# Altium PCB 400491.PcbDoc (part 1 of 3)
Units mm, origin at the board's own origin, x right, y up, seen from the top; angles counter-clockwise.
Board outline 85.6 x 53.98 mm, 4 copper layers (Top Layer, Mid-Layer 1, Mid-Layer 2, Bottom Layer), stack 1.528 mm thick; 280 components, 167 nets, 927 pads, 859 vias.
Unrouted connection lines stored in the file: 24.
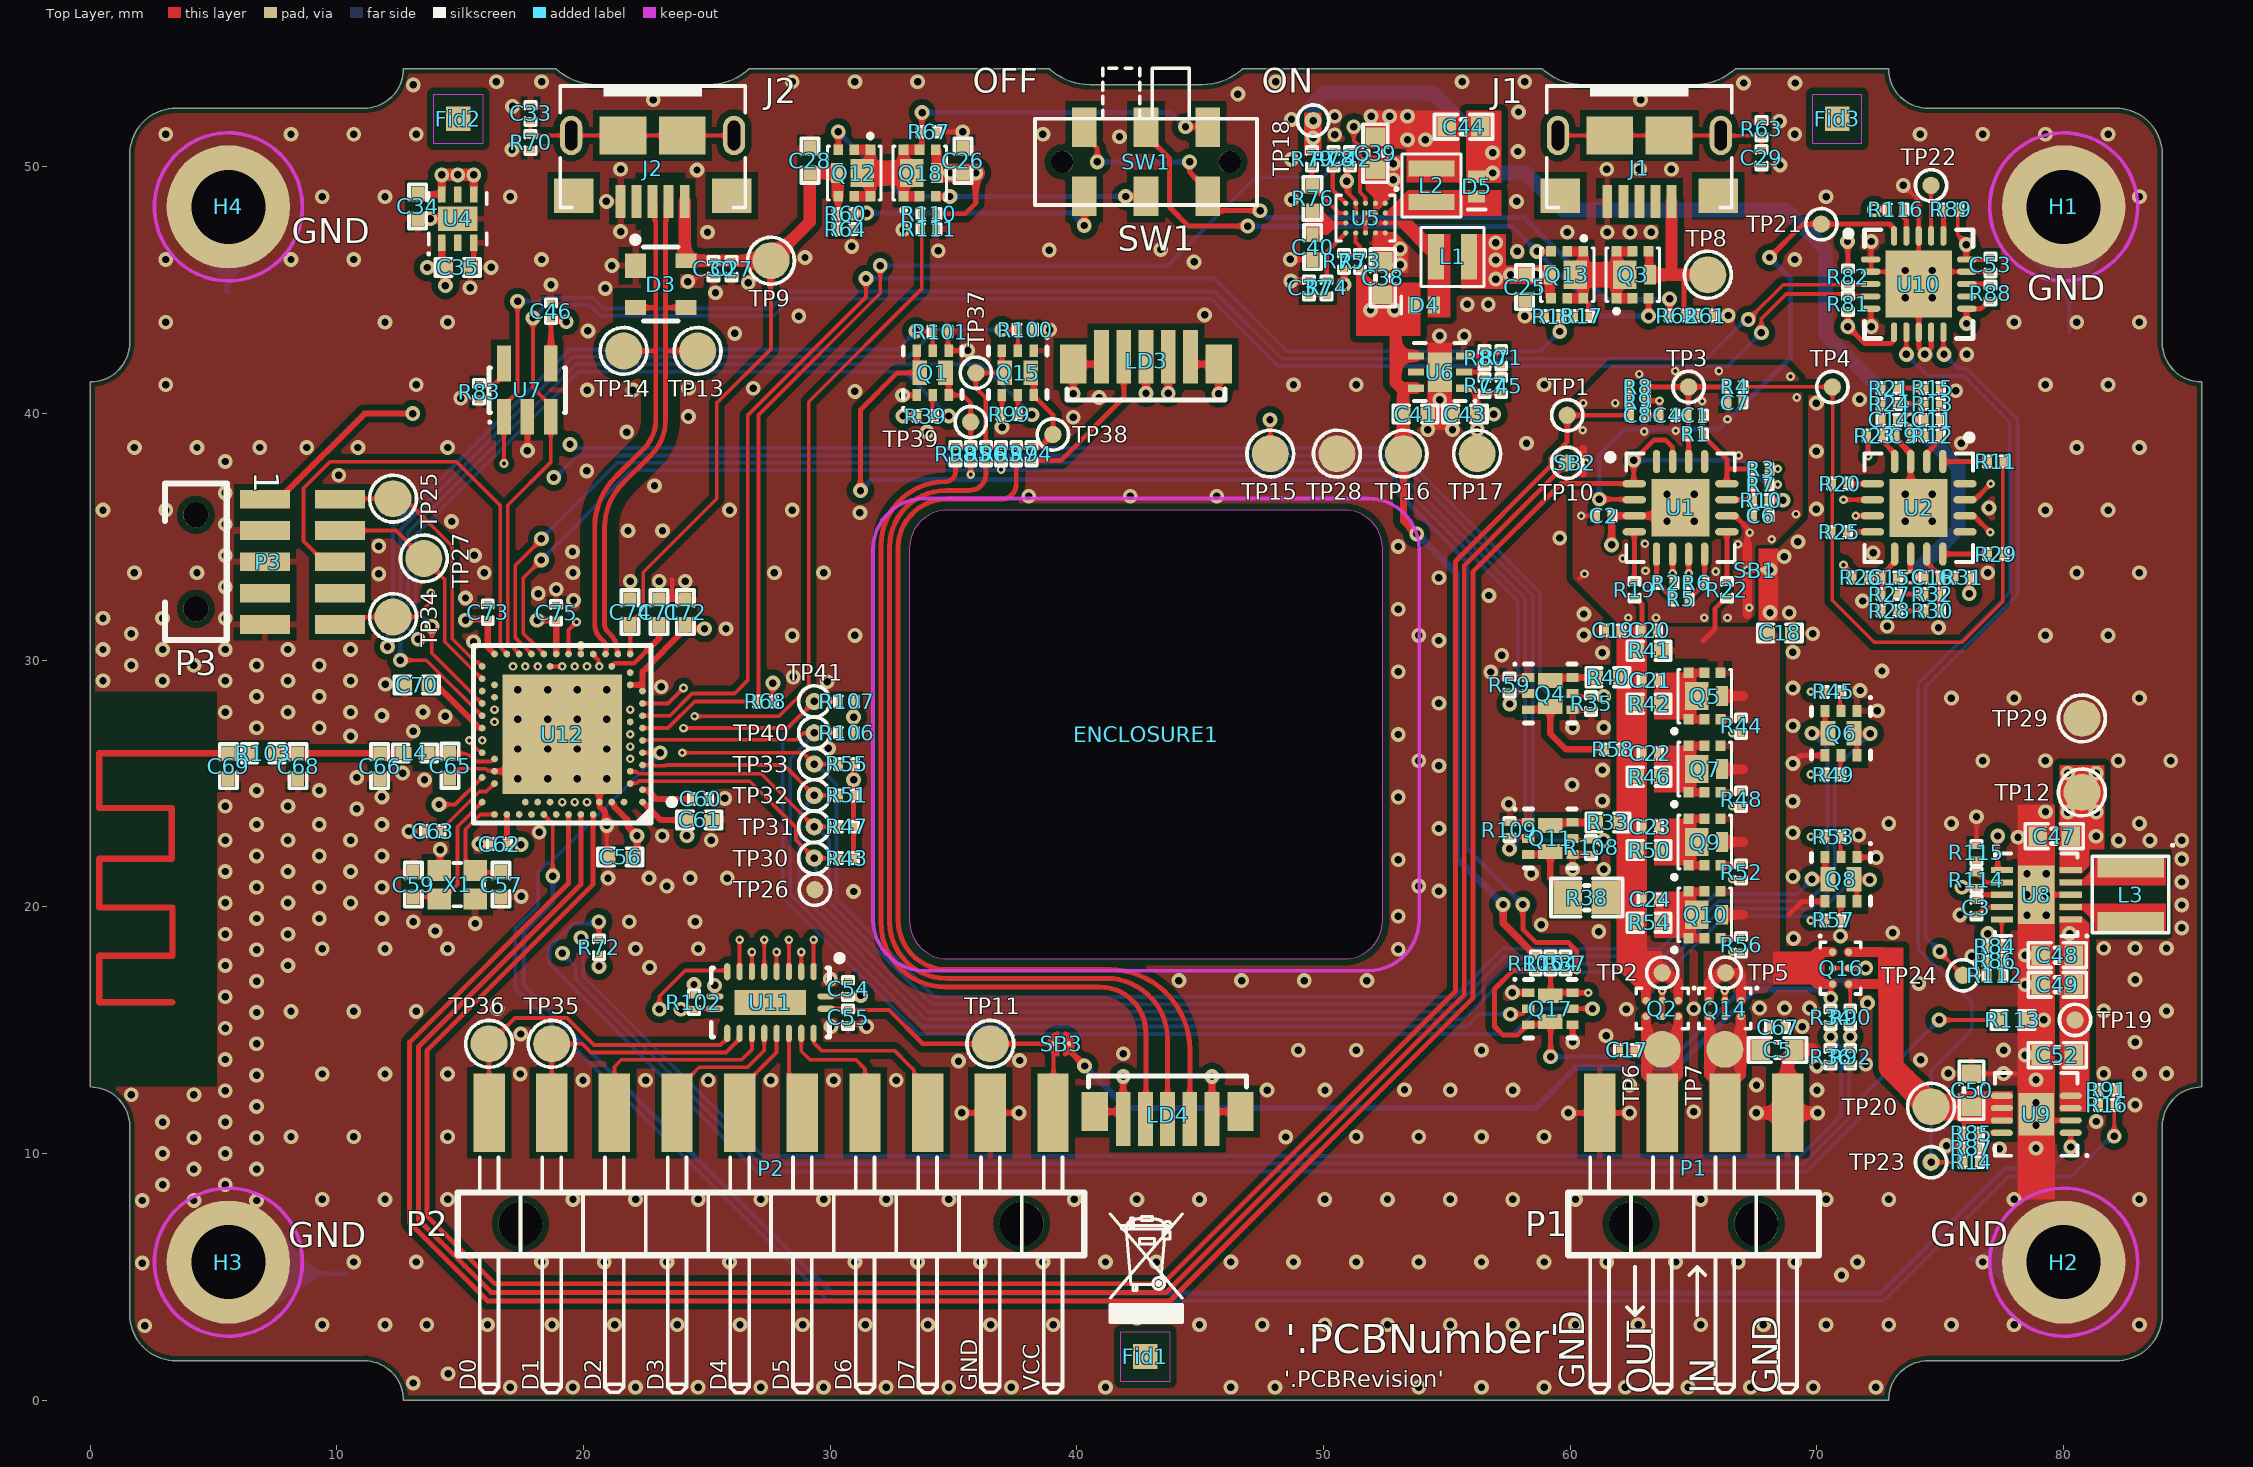
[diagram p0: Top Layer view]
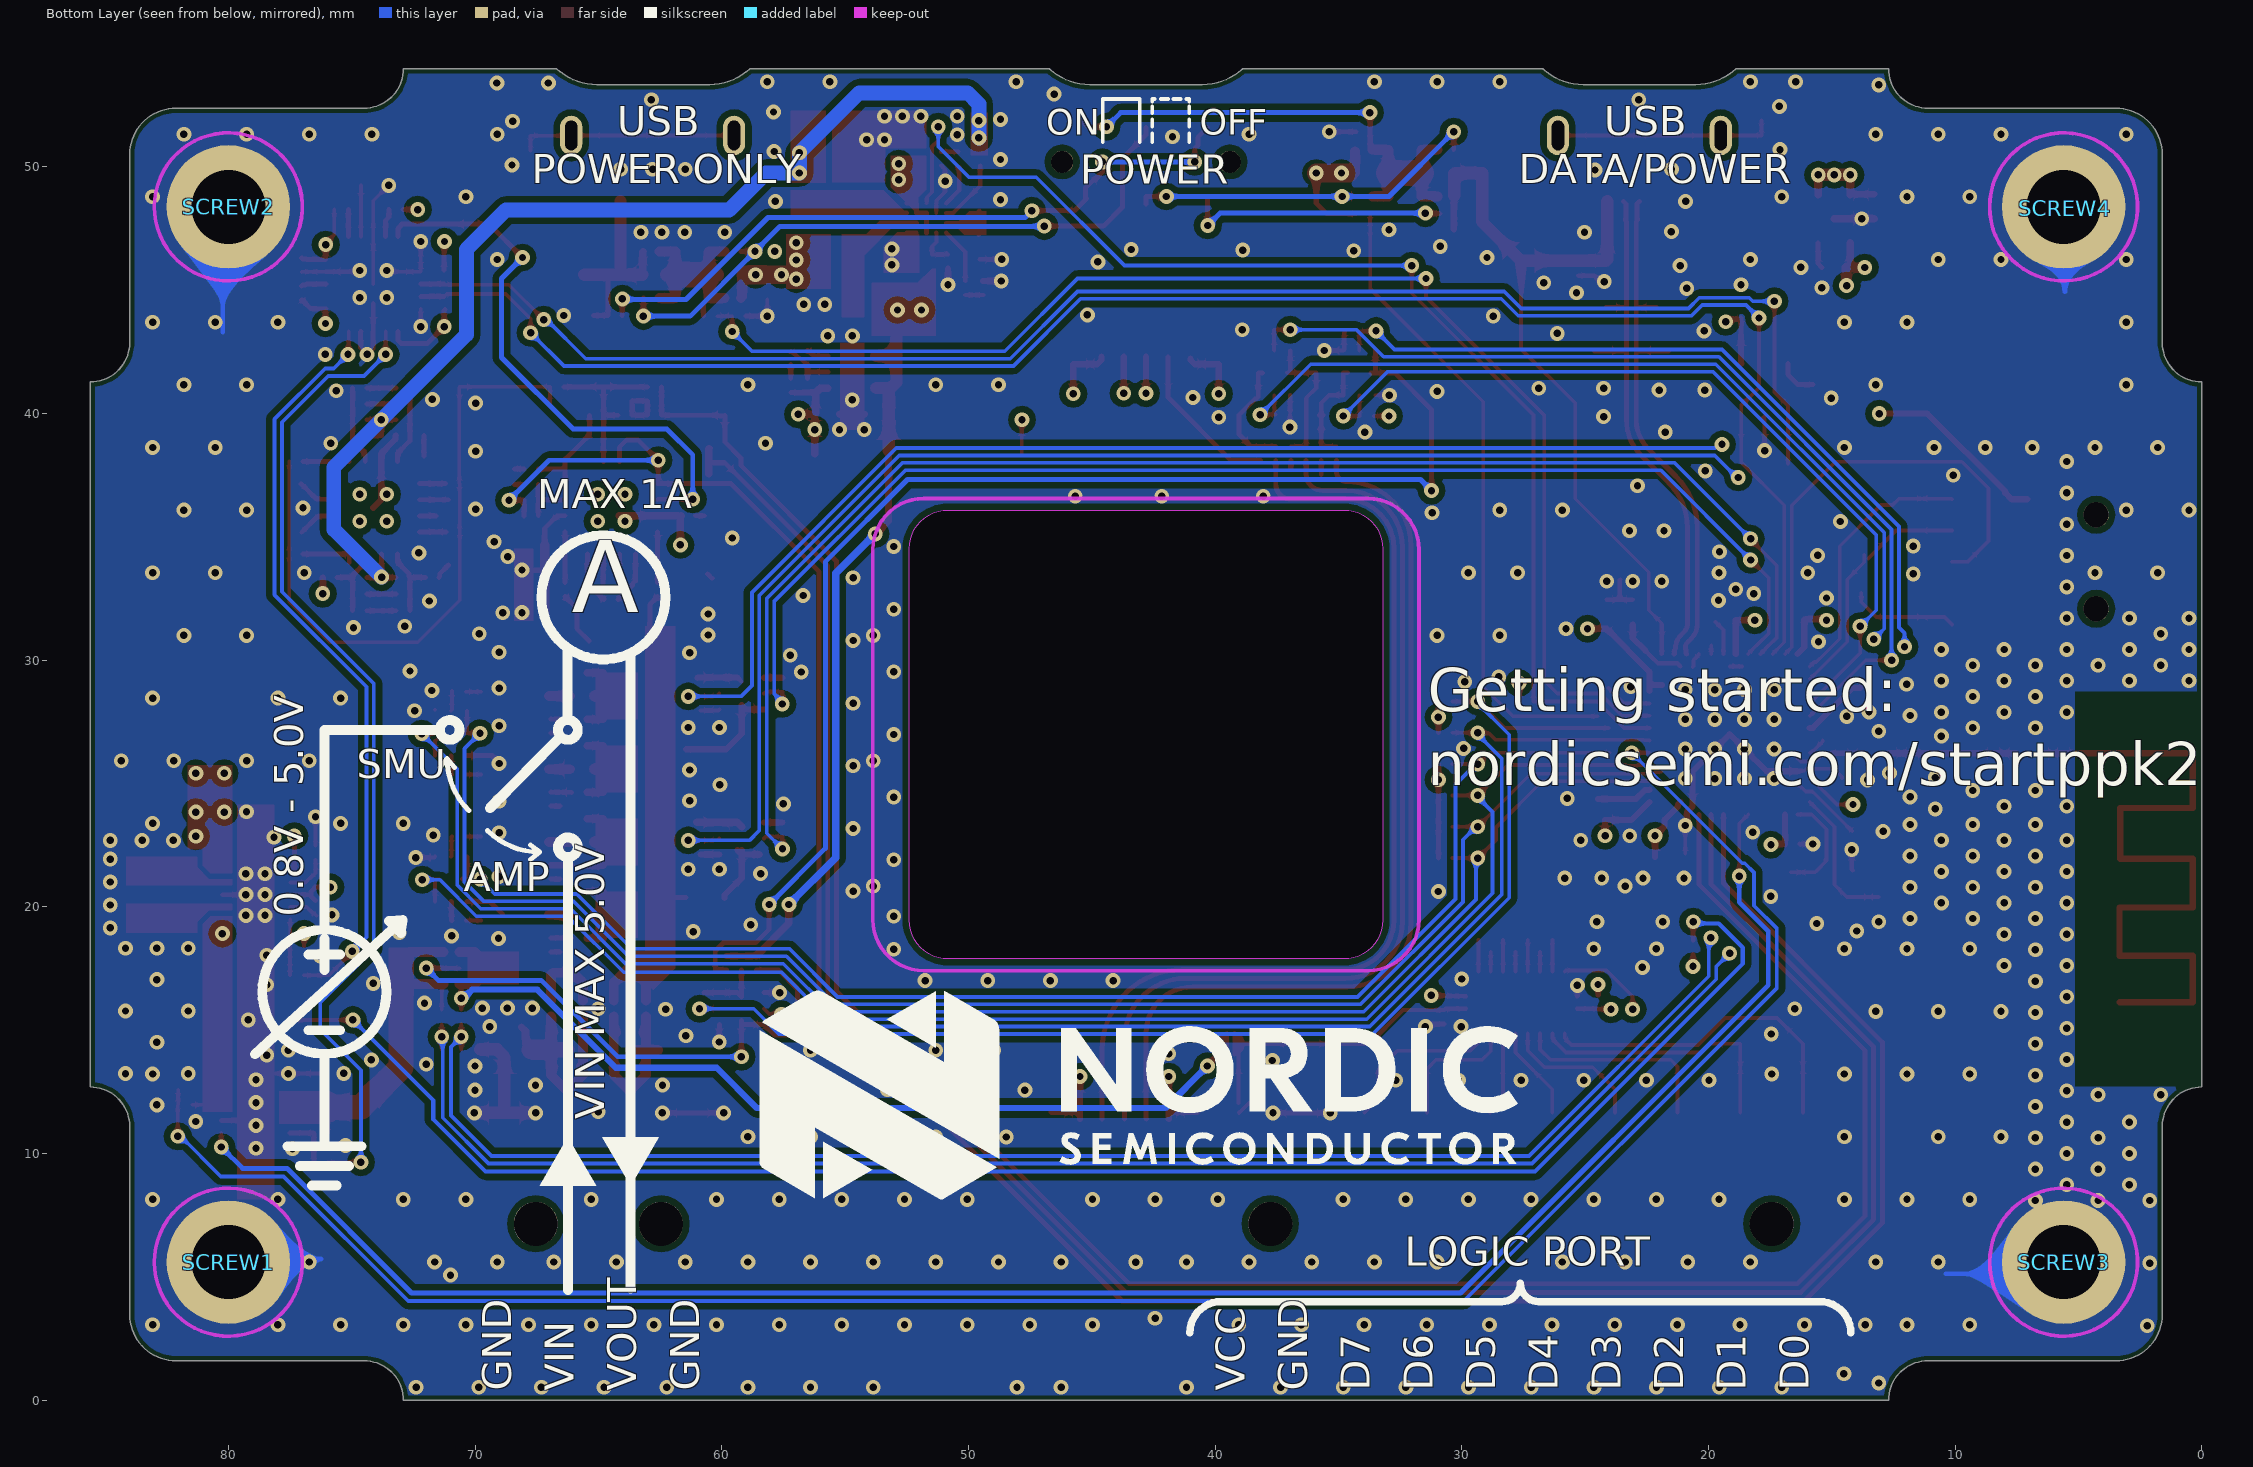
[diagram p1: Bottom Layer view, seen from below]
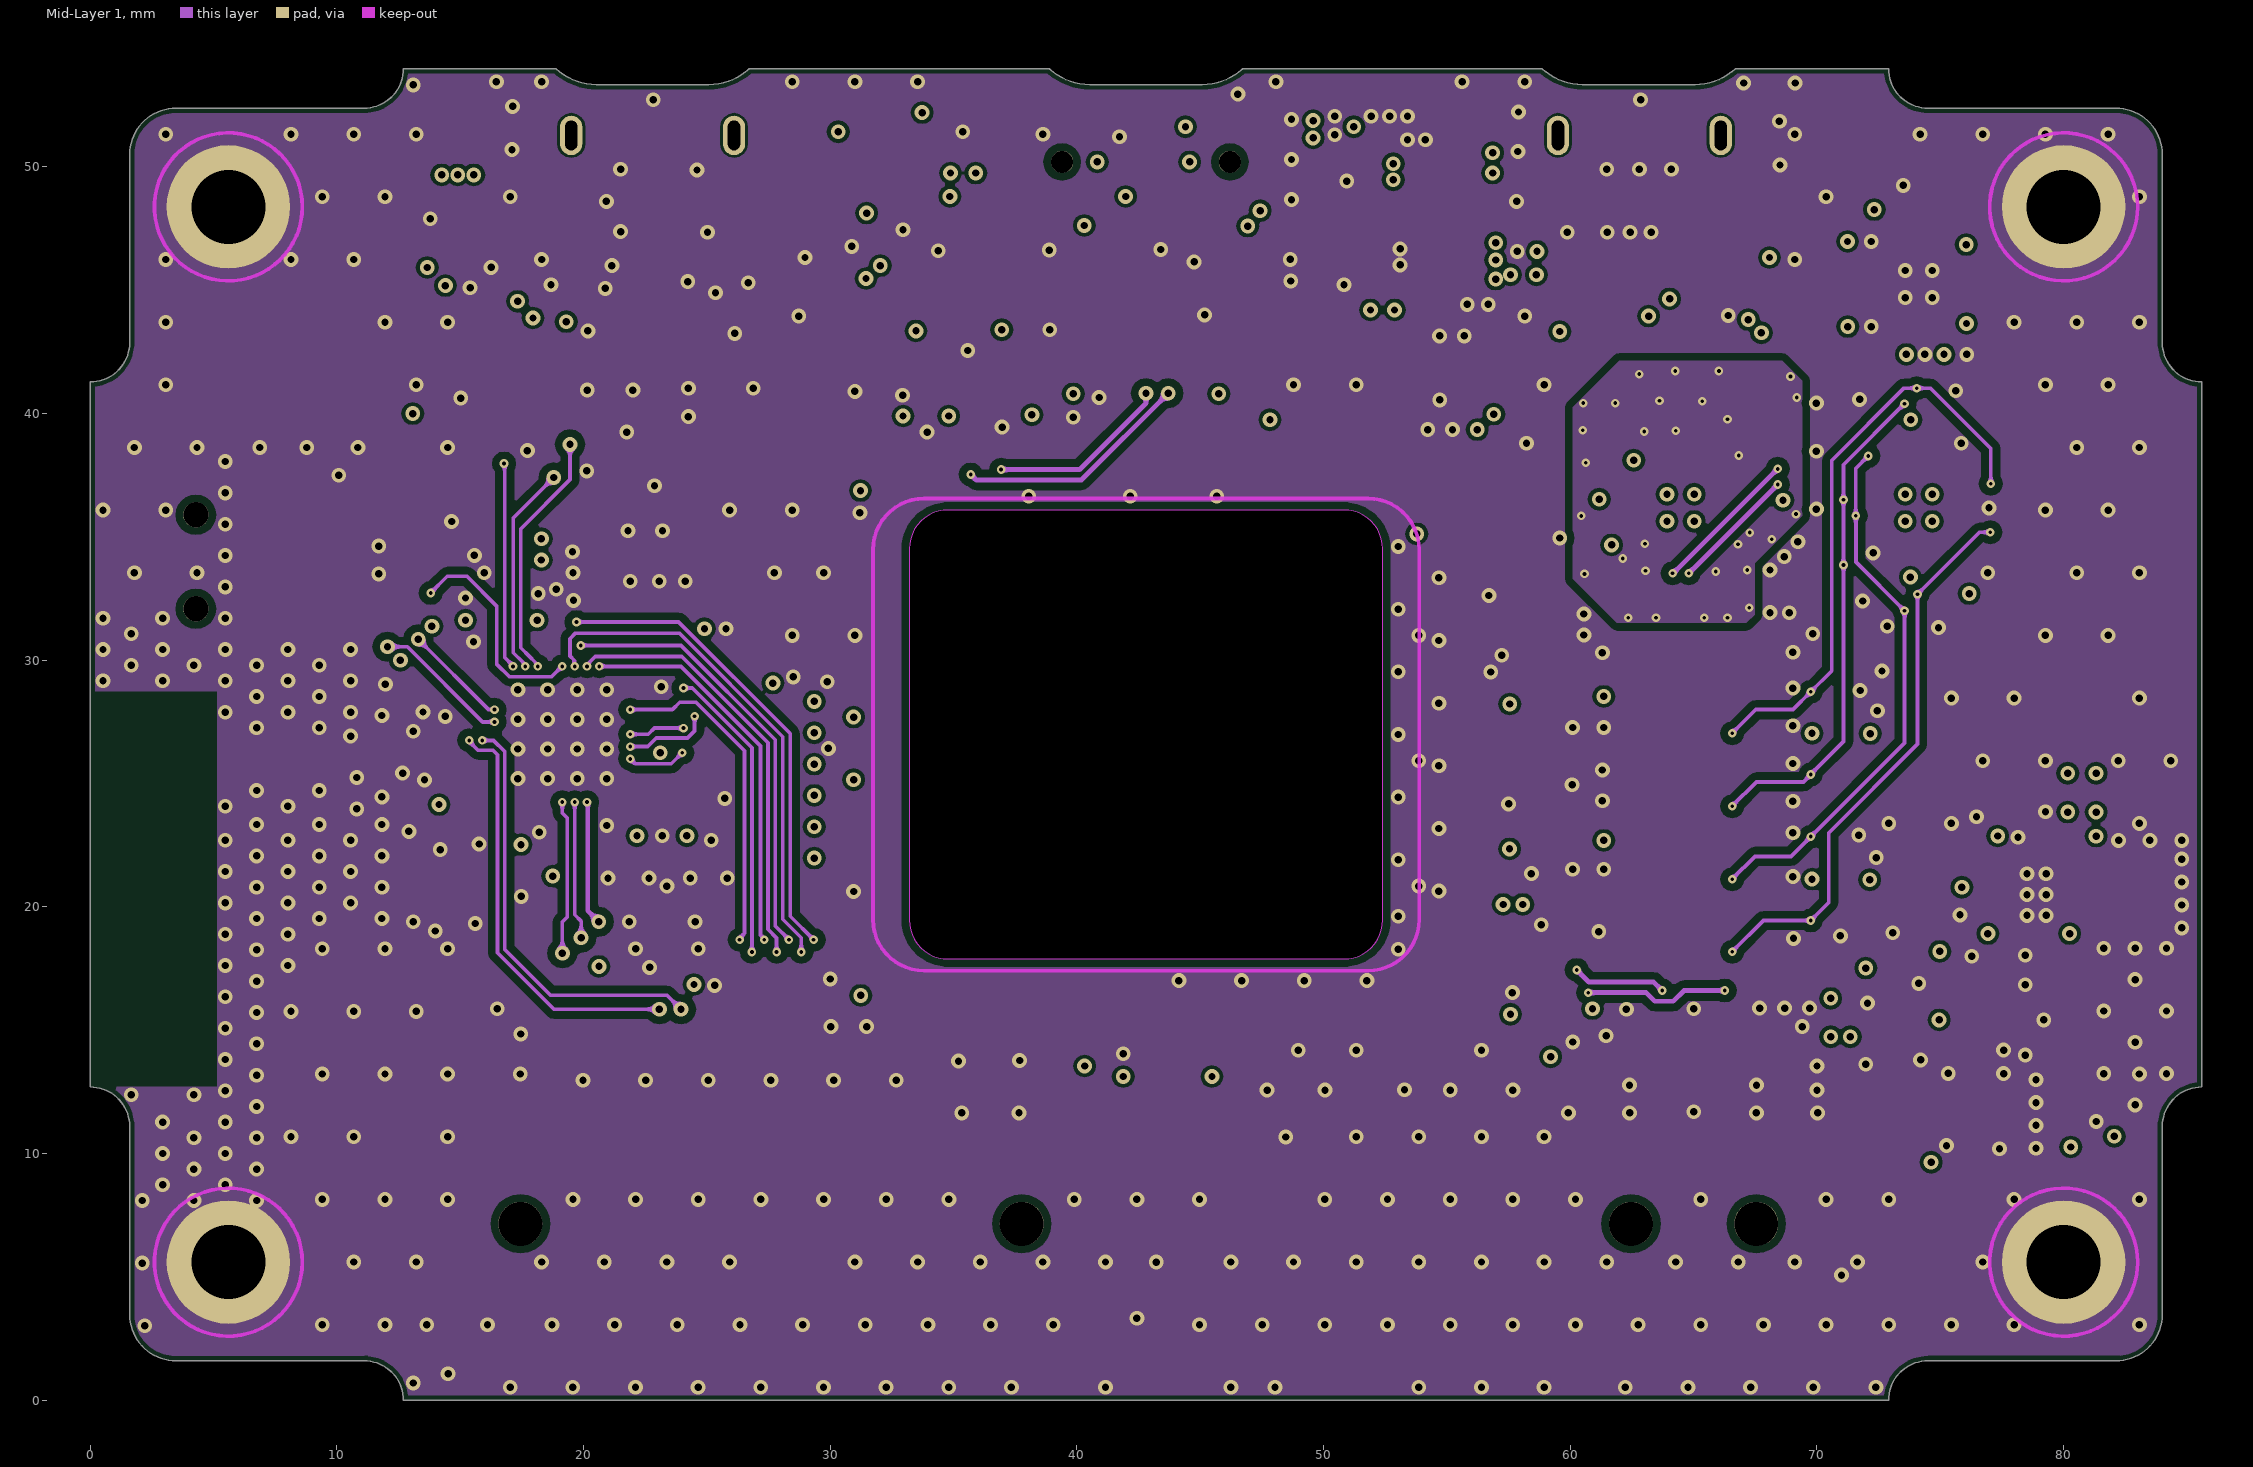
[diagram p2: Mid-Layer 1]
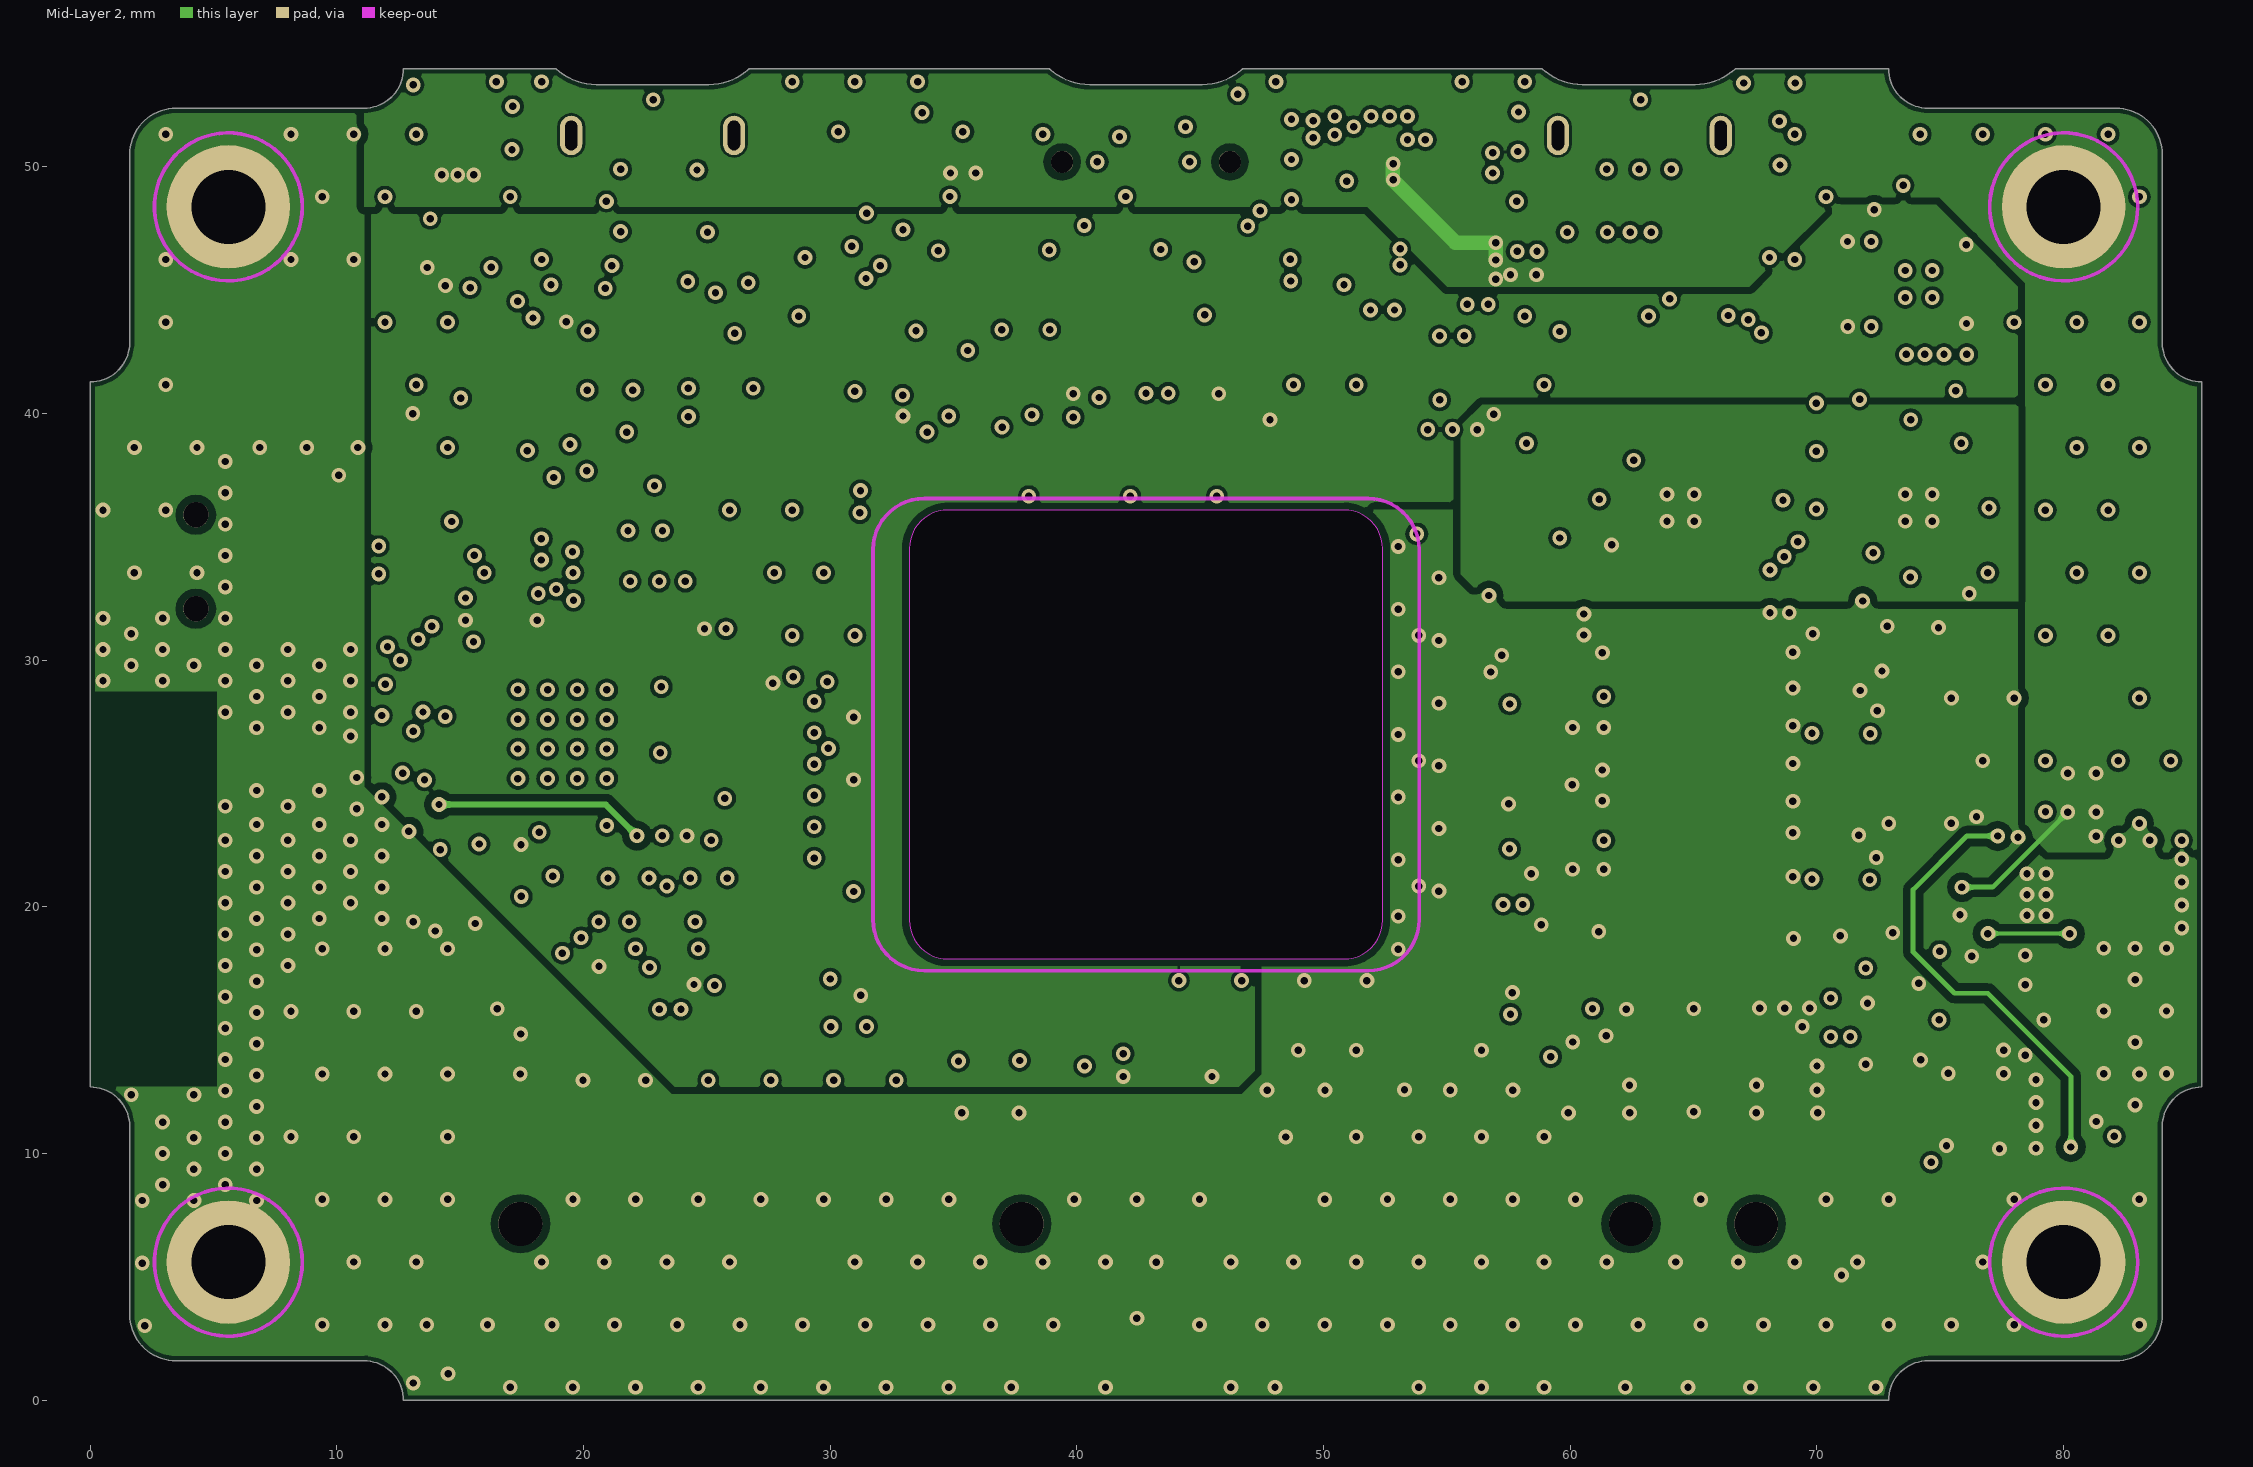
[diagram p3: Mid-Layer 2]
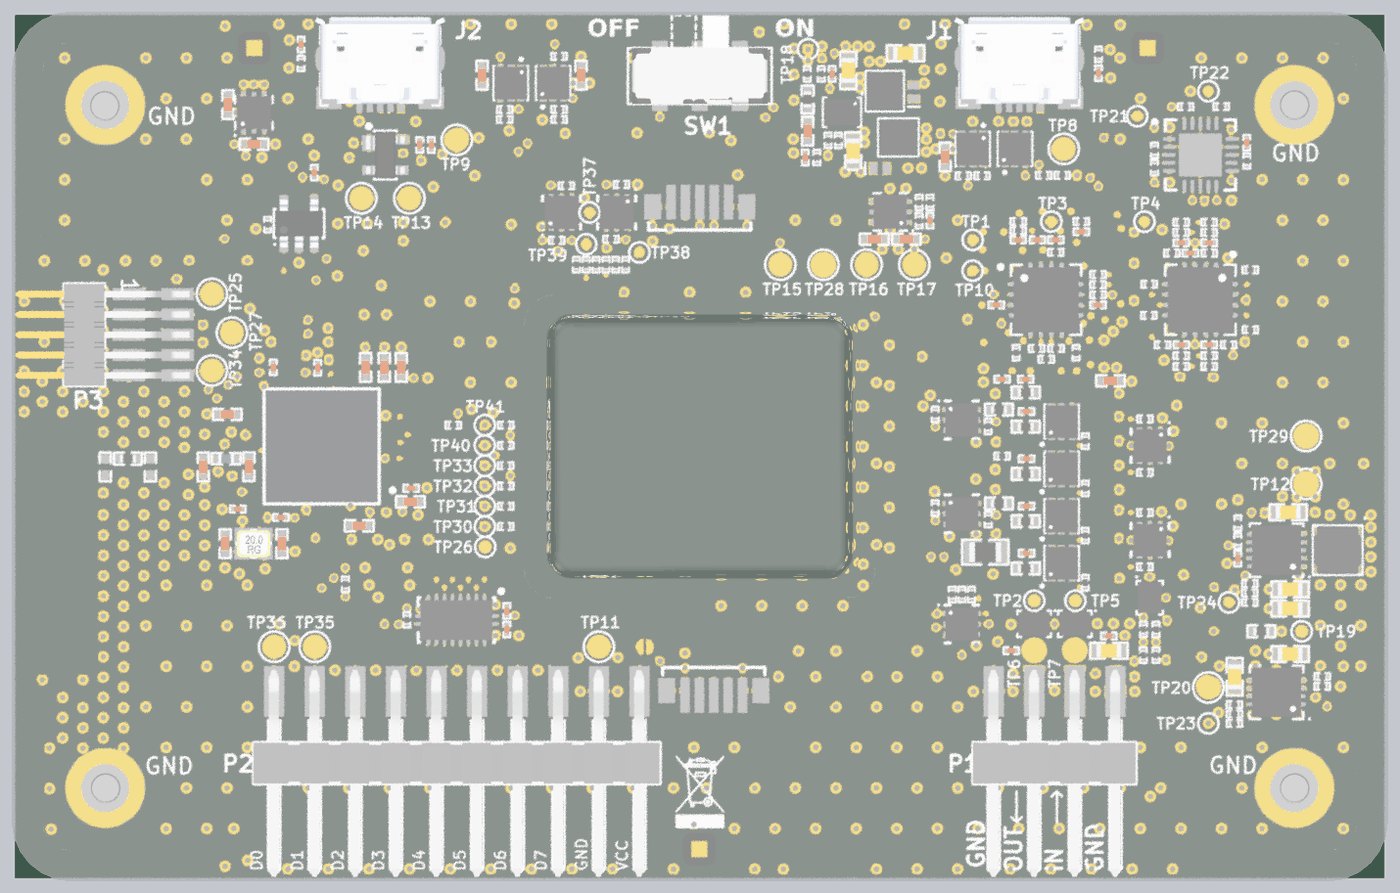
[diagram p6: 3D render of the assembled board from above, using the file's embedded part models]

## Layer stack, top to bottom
Top Solder: solder mask 0.013, SM-003, Dk 3.4
Top Layer: signal copper 0.046
Dielectric1: prepreg 0.073, FR-4, Dk 4.18
Mid-Layer 1: signal copper 0.03
Dielectric2: core 1.23, FR-4, Dk 4.74
Mid-Layer 2: signal copper 0.03
Dielectric3: prepreg 0.073, FR-4, Dk 4.18
Bottom Layer: signal copper 0.046
Bottom Solder: solder mask 0.013, SM-003, Dk 3.4

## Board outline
1.6,11.1 ccw(c0,11.1) 0,12.7 0,41.28 ccw(c0,42.88) 1.6,42.88 1.6,50.5 cw(c3.48,50.5) 3.48,52.38 11.1,52.38 ccw(c11.1,53.98) 12.7,53.98 18.881,53.98 ccw(c20.518,55.736) 20.518,53.336 25.082,53.336 ccw(c25.082,55.736) 26.719,53.98 38.881,53.98 ccw(c40.518,55.735) 40.518,53.335 45.082,53.335 ccw(c45.082,55.735) 46.719,53.98 58.856,53.98 ccw(c60.493,55.736) 60.493,53.336 65.057,53.336 ccw(c65.057,55.736) 66.694,53.98 72.9,53.98 ccw(c74.5,53.98) 74.5,52.38 82.12,52.38 cw(c82.12,50.5) 84,50.5 84,42.88 ccw(c85.6,42.88) 85.6,41.28 85.6,12.7 ccw(c85.6,11.1) 84,11.1 84,3.48 cw(c82.12,3.48) 82.12,1.6 74.5,1.6 ccw(c74.5,0) 72.9,0 12.7,0 ccw(c11.1,0) 11.1,1.6 3.48,1.6 cw(c3.48,3.48) 1.6,3.48
cut-out: 33.2,19.47 ccw(c34.78,19.47) 34.78,17.89 50.82,17.89 ccw(c50.82,19.47) 52.4,19.47 52.4,34.51 ccw(c50.82,34.51) 50.82,36.09 34.78,36.09 ccw(c34.78,34.51) 33.2,34.51

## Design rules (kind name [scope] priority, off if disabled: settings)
AcuteAngle [All] p1: minimum=6.00000000000000E+0001 checktracksonly=TRUE
AssemblyTestPointUsage [All] p1: valid=2 allowmultiple=TRUE
AssemblyTestpoint [All] p1: testpointundercomponent=TRUE minsize=1 maxsize=2.54 preferedsize=1.5 minholesize=0 maxholesize=1 preferedholesize=0.3 testpointgrid=0.025 usegrid=FALSE gridtolerance=0 allowsidetop=TRUE allowsidebottom=TRUE minspacing=2 compbodyclearance=0.127
BoardOutlineClearance [not ( HasFootprint('Switch-Slide-RA-J-Lead-DPDT-8.5x3.5mm') or HasFootprint('USB-Micro-B-RA-SMD-PiP') or HasFootprint('LIST_ANG_1x4') or HasFootprint('MSL0104') or IsKeepOut or InComponent('J7') or InComponent('J1'))] p1: gap=0.2 ignorepadtopadclearanceinfootprint=FALSE
Clearance "Stitching GND" [IsStitchingVia and InNet('GND') vs (IsVia and (Not IsStitchingVia)) Or IsPad] p1: gap=0.15 ignorepadtopadclearanceinfootprint=FALSE
Clearance ANT_Clerance [InNet('ANT') or InNet('RF')] p2: gap=0.25 ignorepadtopadclearanceinfootprint=FALSE
Clearance Clearance_USB [InAnyDifferentialPair vs InPolygon] p3: gap=0.5 ignorepadtopadclearanceinfootprint=FALSE
Clearance Polygon_Clearance_Outer [(InNamedPolygon('Top_Layer-GND')) or (InNamedPolygon('Bottom_Layer-GND'))] p4: gap=0.254 ignorepadtopadclearanceinfootprint=FALSE
Clearance Polygon_Clearance_Inner [InPoly and OnMid] p5: gap=0.3 ignorepadtopadclearanceinfootprint=FALSE
Clearance Clearance_MCU [TouchesRoom('nRF5')] p6: gap=0.145 ignorepadtopadclearanceinfootprint=FALSE
Clearance [All] p7: gap=0.15 ignorepadtopadclearanceinfootprint=FALSE
ComponentClearance [All] p1 off: gap=0.254 collisioncheckmode=3 verticalgap=0.254 showdistances=FALSE
DiffPairsRouting [InDifferentialPair('RFD')] p1: maxlimit=0.2 minlimit=0.15 mostfreqgap=0.18 toplayer_minwidth=0.2 toplayer_maxwidth=0.22 toplayer_prefwidth=0.217 midlayer1_minwidth=0.2 midlayer1_maxwidth=0.22 midlayer1_prefwidth=0.217 midlayer2_minwidth=0.2 midlayer2_maxwidth=0.22 midlayer2_prefwidth=0.217 bottomlayer_minwidth=0.2 bottomlayer_maxwidth=0.22 bottomlayer_prefwidth=0.217 maxuncoupledlength=12.7
FabricationTestPointUsage TestPointUsage [All] p1: valid=2 allowmultiple=FALSE
FabricationTestpoint Testpoint [All] p1: side=3 testpointundercomponent=TRUE minsize=0.75 maxsize=2.54 preferedsize=1.524 minholesize=0 maxholesize=1.016 preferedholesize=0.813 testpointgrid=0.025 allowsidetop=TRUE allowsidebottom=TRUE usegrid=TRUE gridtolerance=0
Height [All] p1 off: minheight=0 maxheight=25.4 prefheight=12.7
HoleSize [All] p1: absolutevalues=TRUE maxlimit=5 minlimit=0.15 maxpercent=80.000 minpercent=20.000
HoleToHoleClearance [All] p1: gap=0.254 allowstackedmicrovias=FALSE
MaxMinImpedance [InNet('ANT')] p1: minimum=45,00 maximum=55,00
MinimumAnnularRing [All] p1 off: minimumring=0.152
MinimumSolderMaskSliver [All] p1: minsoldermaskwidth=0.08
NetAntennae [not InNet('ANT')] p1: netantennaetolerance=0
PolygonConnect PolygonConnect_TP [HasFootprint('TP_SMD_Ø1.0mm') or HasFootprint('TP_SMD_Ø1.5mm')] p1: connectstyle=Direct reliefconductorwidth=0.254 reliefentries=4 polygonreliefangle="90 Angle" airgapwidth=0.254
PolygonConnect [All] p2: thpad.connectstyle=Relief thpad.reliefconductorwidth=0.254 thpad.reliefentries=4 thpad.polygonreliefangle="90 Angle" thpad.airgapwidth=0.254 smdpad.connectstyle=Relief smdpad.reliefconductorwidth=0.254 smdpad.reliefentries=4 smdpad.polygonreliefangle="90 Angle" smdpad.airgapwidth=0.254 via.connectstyle=Direct via.reliefconductorwidth=0.254 via.reliefentries=4 via.polygonreliefangle="90 Angle" via.airgapwidth=0.254
ReturnPath [All] p1: impedanceprofileid={5BC9D8EB-500C-4DB7-B910-E6E0F3DAAD07} _gaplimit=0
RoomDefinition nRF5 [False] p1: confinementstyle=ConfineIn formatcopy=TRUE lockcomponents=FALSE outline 15.625,30.375 22.8,30.375 22.8,23.5 15.625,23.5
RoutingVias [All] p1: holewidth=0.3 width=0.6 viastyle="Through Hole" minholewidth=0.15 minwidth=0.35 maxholewidth=0.7 maxwidth=1.27
SilkToSilkClearance [All] p1: silktosilkclearance=0
SilkToSolderMaskClearance SilkscreenOverComponentPads [IsPad] p1: minsilkscreentomaskgap=0 clearancetoexposedcopper=TRUE
SolderMaskExpansion SolderMaskExpansion_VIA [IsVia and not IsAssyTestpoint] p1: expansion=-1 istentingtop=FALSE
SolderMaskExpansion [All] p2: expansion=0.06 istentingtop=FALSE
UnRoutedNet [All] p1: checkbadconnections=TRUE
ViasUnderSMD [All] p1: allowed=FALSE
Width Width_MCU [TouchesRoom('nRF5')] p1: maxlimit=0.5 minlimit=0.145 preferedwidth=0.2
Width Width_USB [InNet('RFD_N') or InNet('RFD_P')] p2: maxlimit=0.254 minlimit=0.091 preferedwidth=0.254 toplayer_maxwidth=0.233 toplayer_prefwidth=0.198 bottomlayer_maxwidth=0.233 bottomlayer_prefwidth=0.198 impedanceprofiledriven=TRUE impedanceprofileid={5BC9D8EB-500C-4DB7-B910-E6E0F3DAAD07} minimp=50.000000 maximp=50.000000 favimp=50.000000
Width Width_ANT [InNet('ANT') OR InNet('ANT''') OR InNet('RF')] p3: maxlimit=0.287 minlimit=0.103 preferedwidth=0.256 toplayer_prefwidth=0.113 bottomlayer_prefwidth=0.113 impedanceprofiledriven=TRUE impedanceprofileid={18D35FDB-4AA7-49BD-A541-E16E572427C8} impedanceprofilevalue=50.000000 minimp=50.000000 maximp=50.000000 favimp=50.000000
Width [All] p4: maxlimit=2.54 minlimit=0.15 preferedwidth=0.15
16 further rules are at their usual default settings.

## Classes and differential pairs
differential pair class USB2: RFD
component class U_pca70196_mcu: C56 C57 C59 C60 C61 C62 C63 C65 C66 C68 C69 C70 C71 C72 C73 C74 C75 L4 P3 R103 TP25 TP27 TP34 U12 X1
component class U_pca70196_misc: C46 C53 C54 C55 LD3 LD4 P2 Q15 R72 R81 R82 R83 R88 R89 R93 R94 R95 R96 R97 R98 R99 R100 R101 R102 R113 R116 SB3 TP11 TP21 TP22 TP23 TP24 TP35 TP36 TP37 TP38 TP39 U7 U10 U11
component class U_pca70196_power_supply: C3 C25 C26 C27 C28 C29 C30 C33 C34 C35 C37 C38 C39 C40 C41 C42 C43 C44 C45 C47 C48 C49 C50 C52 D3 D4 D5 J1 J2 L1 L2 L3 Q3 Q12 Q13 Q18 R14 R16 R17 R18 R34 R36 R60 R61 R62 R63 R64 R67 R68 R70 R71 R73 R74 R75 R76 R77 R78 R79 R80 R84 R85 R86 R87 R90 R91 R92 R110 R111 R112 R114 R115 SW1 TP8 TP9 TP12 TP13 TP14 TP15 TP16 TP17 TP18 TP19 TP20 TP28 TP29 U4 U5 U6 U8 U9
component class U_pca70196_current_measurement: C5 C17 C18 C19 C20 C21 C22 C23 C24 C67 P1 Q1 Q2 Q4 Q5 Q6 Q7 Q8 Q9 Q10 Q11 Q14 Q16 Q17 R33 R35 R37 R38 R39 R40 R41 R42 R43 R44 R45 R46 R47 R48 R49 R50 R51 R52 R53 R54 R55 R56 R57 R58 R59 R104 R105 R106 R107 R108 R109 TP6 TP7 TP30 TP31 TP32 TP33 TP40 TP41
component class U_pca70196_current_automatic_switch: C1 C2 C4 C6 C7 C8 C9 C11 C14 C15 C16 R1 R2 R3 R4 R5 R6 R7 R8 R9 R10 R11 R12 R13 R15 R19 R20 R21 R22 R23 R24 R25 R26 R27 R28 R29 R30 R31 R32 SB1 SB2 TP1 TP2 TP3 TP4 TP5 TP10 TP26 U1 U2
component class pca63100_top: ENCLOSURE1 Fid1 Fid2 Fid3 H1 H2 H3 H4 SCREW1 SCREW2 SCREW3 SCREW4
differential pair RFD: +RFD_P -RFD_N

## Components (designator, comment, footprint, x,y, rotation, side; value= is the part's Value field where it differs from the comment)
C1 "2.2pF" CAPC0603X03L_C 65.071,39.931 r180 top locked
C2 "100nF" CAPC0603X03L_C 61.356,35.856 r180 top locked
C3 "100nF" CAPC0603X03L_C 76.465,19.969 r270 top locked
C4 "1.0nF" CAPC0603X03L_C 63.921,39.931 r0 top locked
C5 "10µF" CAPC1608X06L 68.4,14.2 r0 top locked
C6 "2.2pF" CAPC0603X03L_C 67.721,35.856 r180 top locked
C7 "2.2nF" CAPC0603X03L_C 66.675,40.444 r0 top locked
C8 "1.0nF" CAPC0603X03L_C 62.725,39.931 r180 top locked
C9 "100nF" CAPC0603X03L_C 73.5,39.106 r180 top locked
C11 "470pF" CAPC0603X03L_C 74.675,39.748 r0 top locked
C14 "470pF" CAPC0603X03L_C 72.925,39.748 r180 top locked
C15 "470pF" CAPC0603X03L_C 72.925,33.356 r180 top locked
C16 "470pF" CAPC0603X03L_C 74.675,33.356 r0 top locked
C17 "10nF" CAPC0603X03L_C 62.29,14.2 r0 top locked
C18 "4.7µF" CAPC1005X04L 68.496,31.106 r0 top locked
C19 "10nF" CAPC0603X03L_C 61.721,31.206 r0 top locked
C20 "10nF" CAPC0603X03L_C 63.196,31.206 r180 top locked
C21 "100nF" CAPC0603X03L_C 63.246,29.181 r180 top locked
C22 "100nF" CAPC0603X03L_C 63.246,26.223 r180 top locked
C23 "100nF" CAPC0603X03L_C 63.246,23.256 r180 top locked
C24 "100nF" CAPC0603X03L_C 63.246,20.306 r180 top locked
C25 "4.7µF" CAPC1005X04L 58.15,45.125 r90 top locked
C26 "4.7µF" CAPC1005X04L 35.375,50.25 r270 top locked
C27 "100nF" CAPC0603X03L_C 26,45.875 r270 top locked
C28 "4.7µF" CAPC1005X04L 29.175,50.25 r90 top locked
C29 "4.7nF" CAPC0603X03L_C 67.75,50.375 r270 top locked
C30 "10nF" CAPC0603X03L_C 25.275,45.875 r270 top locked
C33 "4.7nF" CAPC0603X03L_C 17.85,52.165 r90 top locked
C34 "4.7µF" CAPC1005X04L 13.275,48.4 r270 top locked
C35 "4.7µF" CAPC1005X04L 14.9,45.922 r180 top locked
C37 "2.2nF" CAPC0603X03L_C 49.4,45.09 r270 top locked
C38 "10µF" CAPC1608X06L 52.4,45.5 r270 top locked
C39 "10µF" CAPC1608X06L 52.1,50.55 r90 top locked
C40 "1.0µF" CAPC1005X04L 49.55,46.75 r90 top locked
C41 "4.7µF" CAPC1005X04L 53.725,39.975 r0 top locked
C42 "2.2nF" CAPC0603X03L_C 51.075,50.325 r90 top locked
C43 "4.7µF" CAPC1005X04L 55.725,39.975 r0 top locked
C44 "10µF" CAPC1608X06L 55.675,51.625 r0 top locked
C45 "1.0µF" CAPC0603X03L_C 57.2,41.135 r270 top locked
C46 "100nF" CAPC0603X03L_C 18.675,44.15 r90 top locked
C47 "10µF" CAPC1608X06L 79.615,22.869 r180 top locked
C48 "10µF" CAPC1608X06L 79.74,18.044 r180 top locked
C49 "10µF" CAPC1608X06L 79.74,16.844 r180 top locked
C50 "10µF" CAPC1608X06L 76.265,12.569 r90 top locked
C52 "10µF" CAPC1608X06L 79.74,13.994 r180 top locked
C53 "100nF" CAPC0603X03L_C 77.026,46.024 r90 top locked
C54 "100nF" CAPC0603X03L_C 30.725,16.692 r90 top locked
C55 "100nF" CAPC0603X03L_C 30.725,15.533 r270 top locked
C56 "1.0µF" CAPC1005X04L 21.49,22.025 r0 top locked
C57 "12pF" CAPC1005X04L 16.657,20.905 r270 top locked
C59 "12pF" CAPC1005X04L 13.101,20.905 r90 top locked
C60 "100nF" CAPC0603X03L_C 24.74,24.375 r0 top locked
C61 "1.0µF" CAPC1005X04L 24.69,23.525 r0 top locked
C62 "100nF" CAPC0603X03L_C 16.59,22.55 r180 top locked
C63 "100pF" CAPC0603X03L_C 13.89,23.075 r180 top locked
C65 "0.8pF" CAPC1005X04L 14.588,25.725 r90 top locked
C66 "0.5pF" CAPC1005X04L 11.733,25.708 r90 top locked
C67 "100nF" CAPC0603X03L_C 68.4,15.125 r0 top locked
C68 "N.C." CAPC1005X04L_NC 8.425,25.708 r90 top locked
C69 "N.C." CAPC1005X04L_NC 5.6,25.708 r90 top locked
C70 "820pF" CAPC1005X04L 13.24,29 r180 top locked
C71 "4.7µF" CAPC1005X04L 23.065,31.95 r90 top locked
C72 "4.7µF" CAPC1005X04L 24.125,31.95 r90 top locked
C73 "100nF" CAPC0603X03L_C 16.115,31.95 r90 top locked
C74 "4.7µF" CAPC1005X04L 21.89,31.95 r90 top locked
C75 "100nF" CAPC0603X03L_C 18.89,31.925 r90 top locked
D3 "PRTR5V0U2X" SOT190P230X110-4L 23.125,45.247 r0 top locked
D4 "PMEG2005AELD" DFN1006D-2 54.075,44.4 r0 top locked
D5 "PMEG2005AELD" DFN1006D-2 56.2,49.2 r90 top locked
ENCLOSURE1 "Plastic Enclosure" ENCLOSURE_PPK2 42.8,26.99 r0 top
Fid1 "Fiducial mark" Fiducial_Round-Square 42.775,1.775 r90 top locked
Fid2 "Fiducial mark" Fiducial_Round-Square 14.925,51.95 r90 top locked
Fid3 "Fiducial mark" Fiducial_Round-Square 70.825,51.95 r90 top locked
H1 "3mm,P.T." HOLE_PT_3MM 80,48.38 r0 top locked
H2 "3mm,P.T." HOLE_PT_3MM 80,5.6 r270 top locked
H3 "3mm,P.T." HOLE_PT_3MM 5.6,5.6 r180 top locked
H4 "3mm,P.T." HOLE_PT_3MM 5.6,48.38 r90 top locked
J1 "MicroUSB-B" USB-Micro-B-RA-SMD-PiP 62.8,48.6 r270 top locked
J2 "MicroUSB-B" USB-Micro-B-RA-SMD-PiP 22.8,48.6 r270 top locked
L1 "4.7µH" IND_EPL2014 55.225,46.35 r180 top locked
L2 "4.7µH" IND_EPL2014 54.375,49.25 r270 top locked
L3 "1.5µH" TY-NR3015 82.715,20.5 r270 top locked
L4 "4.7nH" INDC1005X04L 13.166,26.233 r180 top locked
LD3 "LED RGB" MSL0104 42.8,42.3 r180 top locked
LD4 "LED RGB" MSL0104 43.675,11.4 r0 top locked
P1 "Pin List 1x4, Angled" LIST_ANG_1x4-SMD-2.54MM 65,11.65 r0 top locked
P2 "Pin List 1x10, Angled" LIST_ANG_1x10-SMD-2.54MM 27.6,11.65 r0 top locked
P3 "Pin Header 2x5" HDR_2x5-SMD-1.27mm-ANG 8.605,33.99 r270 top locked
Q1 "DMN2050LFDB" DFN65P200X60_HS-6N 34.15,41.65 r90 top locked
Q2 "EFC6604R" BGA6C65P2X3_146X191X22 63.726,15.881 r270 top locked
Q3 "DMP1009UFDF" UDFN65P200X200X60_HS-6N 62.525,45.625 r90 top locked
Q4 "DMN2050LFDB" DFN65P200X60_HS-6N 59.19,28.65 r0 top locked
Q5 "DMP1009UFDF" UDFN65P200X200X60_HS-6N 65.446,28.548 r90 top locked
Q6 "DMN2050LFDB" DFN65P200X60_HS-6N 70.975,27.043 r270 top locked
Q7 "DMP1009UFDF" UDFN65P200X200X60_HS-6N 65.446,25.59 r90 top locked
Q8 "DMN2050LFDB" DFN65P200X60_HS-6N 70.975,21.126 r270 top locked
Q9 "DMP1009UFDF" UDFN65P200X200X60_HS-6N 65.446,22.631 r90 top locked
Q10 "DMP1009UFDF" UDFN65P200X200X60_HS-6N 65.446,19.681 r90 top locked
Q11 "DMN2050LFDB" DFN65P200X60_HS-6N 59.19,22.775 r0 top locked
Q12 "DMP1009UFDF" UDFN65P200X200X60_HS-6N 30.975,49.75 r270 top locked
Q13 "DMP1009UFDF" UDFN65P200X200X60_HS-6N 59.875,45.625 r270 top locked
Q14 "EFC6604R" BGA6C65P2X3_146X191X22 66.266,15.881 r270 top locked
Q15 "DMN2050LFDB" DFN65P200X60_HS-6N 37.6,41.65 r270 top locked
Q16 "EFC6604R" BGA6C65P2X3_146X191X22 70.956,17.519 r0 top locked
Q17 "DMN2050LFDB" DFN65P200X60_HS-6N 59.19,15.875 r0 top locked
Q18 "DMP1009UFDF" UDFN65P200X200X60_HS-6N 33.625,49.75 r90 top locked
R1 "20k" RESC0603X03L_C 65.071,39.156 r180 top locked
R2 "20k" RESC0603X03L_C 63.871,33.131 r0 top locked
R3 "10k" RESC0603X03L_C 67.721,37.756 r180 top locked
R4 "1k" RESC0603X03L_C 66.675,41.081 r0 top locked
R5 "2.1k" RESC0603X03L_C 64.485,32.463 r180 top locked
R6 "20k" RESC0603X03L_C 65.096,33.131 r180 top locked
R7 "10k" RESC0603X03L_C 67.721,37.123 r180 top locked
R8 "10k" RESC0603X03L_C 62.725,41.081 r180 top locked
R9 "10k" RESC0603X03L_C 62.725,40.506 r180 top locked
R10 "20k" RESC0603X03L_C 67.721,36.49 r180 top locked
R11 "8k2" RESC0603X03L_C 77.25,38.056 r180 top locked
R12 "3k" RESC0603X03L_C 74.675,39.106 r180 top locked
R13 "6k8" RESC0603X03L_C 74.675,40.389 r0 top locked
R14 "220k" RESC0603X03L_C 76.25,9.65 r180 top locked
R15 "8k2" RESC0603X03L_C 74.675,41.031 r180 top locked
R16 "120k" RESC0603X03L_C 81.75,11.975 r180 top locked
R17 "56k" RESC0603X03L_C 60.46,43.95 r180 top locked
R18 "100k" RESC0603X03L_C 59.295,43.95 r0 top locked
R19 "4k7" RESC0603X03L_C 62.596,32.861 r270 top locked
R20 "8k2" RESC0603X03L_C 70.92,37.156 r0 top locked
R21 "3k" RESC0603X03L_C 72.925,41.031 r0 top locked
R22 "4k7" RESC0603X03L_C 66.346,32.861 r270 top locked
R23 "6k8" RESC0603X03L_C 72.35,39.106 r0 top locked
R24 "8k2" RESC0603X03L_C 72.925,40.389 r0 top locked
R25 "8k2" RESC0603X03L_C 70.9,35.206 r0 top locked
R26 "3k" RESC0603X03L_C 71.75,33.356 r180 top locked
R27 "6k8" RESC0603X03L_C 72.925,32.681 r180 top locked
R28 "8k2" RESC0603X03L_C 72.925,32.006 r0 top locked
R29 "8k2" RESC0603X03L_C 77.25,34.306 r180 top locked
R30 "3k" RESC0603X03L_C 74.675,32.006 r180 top locked
R31 "6k8" RESC0603X03L_C 75.885,33.356 r180 top locked
R32 "6k8" RESC0603X03L_C 74.675,32.681 r180 top locked
R33 "1k" RESC1005X04L 61.521,23.425 r180 top locked
R34 "120k" RESC0603X03L_C 70.556,15.533 r90 top locked
R35 "1M0" RESC0603X03L_C 60.845,28.25 r90 top locked
R36 "30k" RESC0603X03L_C 70.556,13.925 r90 top locked
R37 "100k" RESC0603X03L_C 59.8,17.725 r270 top locked
R38 "100R" RESC2012X11L 60.665,20.375 r0 top locked
R39 "1M0" RESC0603X03L_C 33.85,39.9 r180 top locked
R40 "100k" RESC1005X04L 61.521,29.306 r0 top locked
R41 "1k" RESC1005X04L 63.196,30.381 r180 top locked
R42 "110R" RESC1005X04L 63.196,28.231 r180 top locked
R43 "4k7" RESC0603X03L_C 30.66,21.98 r0 top locked
R44 "47R" RESC0603X03L_C 66.921,27.328 r90 top locked
R45 "47R" RESC0603X03L_C 70.65,28.718 r180 top locked
R46 "11R" RESC1005X04L 63.196,25.273 r180 top locked
R47 "4k7" RESC0603X03L_C 30.66,23.25 r0 top locked
R48 "47R" RESC0603X03L_C 66.921,24.37 r90 top locked
R49 "47R" RESC0603X03L_C 70.65,25.368 r180 top locked
R50 "1R0" RESC1005X04L 63.196,22.306 r180 top locked
R51 "4k7" RESC0603X03L_C 30.66,24.52 r0 top locked
R52 "47R" RESC0603X03L_C 66.921,21.411 r90 top locked
R53 "47R" RESC0603X03L_C 70.65,22.851 r180 top locked
R54 "0R051" RESC1005X04L 63.196,19.356 r0 top locked
R55 "4k7" RESC0603X03L_C 30.66,25.79 r0 top locked
R56 "47R" RESC0603X03L_C 66.921,18.461 r90 top locked
R57 "47R" RESC0603X03L_C 70.65,19.451 r180 top locked
R58 "10k" RESC0603X03L_C 61.721,26.392 r180 top locked
R59 "1M0" RESC0603X03L_C 57.535,29 r270 top locked
R60 "10k" RESC0603X03L_C 30.6,48.1 r180 top locked
R61 "100k" RESC0603X03L_C 65.475,43.975 r0 top locked
R62 "10k" RESC0603X03L_C 64.325,43.975 r180 top locked
R63 "1M0" RESC0603X03L_C 67.75,51.55 r90 top locked
R64 "1M0" RESC0603X03L_C 30.6,47.475 r0 top locked
R67 "100k" RESC0603X03L_C 34,51.425 r0 top locked
R68 "100k" RESC0603X03L_C 27.375,28.33 r180 top locked
R70 "1M0" RESC0603X03L_C 17.85,50.99 r270 top locked
R71 "1k" RESC0603X03L_C 57.2,42.265 r90 top locked
R72 "10k" RESC0603X03L_C 20.625,18.365 r270 top locked
R73 "180k" RESC0603X03L_C 51.475,46.165 r270 top locked
R74 "56k" RESC0603X03L_C 50.125,45.09 r90 top locked
R75 "20k" RESC0603X03L_C 50.825,46.165 r90 top locked
R76 "160k" RESC1005X04L 49.55,48.725 r270 top locked
R77 "330k" RESC0603X03L_C 56.525,41.135 r270 top locked
R78 "56k" RESC0603X03L_C 50.4,50.325 r270 top locked
R79 "560k" RESC0603X03L_C 49.525,50.325 r270 top locked
R80 "68k" RESC0603X03L_C 56.525,42.265 r270 top locked
R81 "4k7" RESC0603X03L_C 71.25,44.46 r270 top locked
R82 "4k7" RESC0603X03L_C 71.25,45.54 r90 top locked
R83 "100k" RESC0603X03L_C 15.763,40.884 r90 top locked
R84 "330k" RESC0603X03L_C 77.215,18.409 r180 top locked
R85 "330k" RESC0603X03L_C 76.25,10.825 r180 top locked
R86 "33k" RESC0603X03L_C 77.215,17.819 r0 top locked
R87 "82k" RESC0603X03L_C 76.25,10.237 r0 top locked
R88 "100k" RESC0603X03L_C 77.026,44.884 r270 top locked
R89 "0R" RESC0603X03L_C 75.425,48.274 r0 top locked
R90 "120k" RESC0603X03L_C 71.35,15.533 r90 top locked
R91 "30k" RESC0603X03L_C 81.75,12.588 r0 top locked
R92 "30k" RESC0603X03L_C 71.35,13.925 r90 top locked
R93 "180R" RESC0603X03L_C 36.925,38.375 r270 top locked
R94 "47R" RESC0603X03L_C 38.155,38.375 r270 top locked
R95 "47R" RESC0603X03L_C 35.695,38.375 r270 top locked
R96 "180R" RESC0603X03L_C 36.31,38.375 r270 top locked
R97 "47R" RESC0603X03L_C 37.54,38.375 r270 top locked
R98 "47R" RESC0603X03L_C 35.08,38.375 r270 top locked
R99 "1M0" RESC0603X03L_C 37.25,39.975 r0 top locked
R100 "1M0" RESC0603X03L_C 37.9,43.4 r180 top locked
R101 "1M0" RESC0603X03L_C 34.45,43.325 r180 top locked
R102 "100k" RESC0603X03L_C 24.475,16.14 r90 top locked
R103 "0R" RESC1005X04L 7.015,26.233 r180 top locked
R104 "100k" RESC0603X03L_C 59.2,17.725 r90 top locked
R105 "100k" RESC0603X03L_C 58.6,17.725 r90 top locked
R106 "1M0" RESC0603X03L_C 30.66,27.06 r0 top locked
R107 "1M0" RESC0603X03L_C 30.66,28.33 r0 top locked
R108 "1M0" RESC0603X03L_C 60.845,22.412 r90 top locked
R109 "1M0" RESC0603X03L_C 57.535,23.137 r270 top locked
R110 "120k" RESC0603X03L_C 34,48.1 r0 top locked
R111 "30k" RESC0603X03L_C 34,47.475 r180 top locked
R112 "330k" RESC0603X03L_C 77.215,17.229 r180 top locked
R113 "10k" RESC1005X04L 77.94,15.419 r180 top locked
R114 "0R" RESC0603X03L_C 76.465,21.084 r270 top locked
R115 "0R" RESC0603X03L_C 76.466,22.195 r270 top locked
R116 "560k" RESC0603X03L_C 73.201,48.274 r180 top locked
SB1 "NetTie_200um" NetTie_200um 67.471,33.656 r0 top locked net-tie
SB2 "NetTie_200um" NetTie_200um 60.175,38 r0 top locked net-tie
SB3 "Solderbridge" Solderbridge 39.362,14.45 r180 top
SCREW1 "Screw" Screw_25x50_pan_tx 80,5.6 r90 bottom
SCREW2 "Screw" Screw_25x50_pan_tx 80,48.38 r90 bottom
SCREW3 "Screw" Screw_25x50_pan_tx 5.6,5.6 r90 bottom
SCREW4 "Screw" Screw_25x50_pan_tx 5.55,48.33 r90 bottom
SW1 "Switch" Switch-Slide-RA-J-Lead-DPDT-8.5x3.5mm 42.8,50.2 r180 top locked
TP1 "Ø0.7mm,SMD" TP_SMD_Ø0.7mm 59.875,39.931 r0 top locked
TP2 "Ø0.7mm,SMD" TP_SMD_Ø0.7mm 63.726,17.331 r0 top locked
TP3 "Ø0.7mm,SMD" TP_SMD_Ø0.7mm 64.796,41.081 r0 top locked
TP4 "Ø0.7mm,SMD" TP_SMD_Ø0.7mm 70.625,41.075 r0 top locked
TP5 "Ø0.7mm,SMD" TP_SMD_Ø0.7mm 66.3,17.331 r0 top locked
TP6 "Ø1.5mm,SMD" TP_SMD_Ø1.5mm 63.726,14.225 r0 top locked
TP7 "Ø1.5mm,SMD" TP_SMD_Ø1.5mm 66.266,14.225 r0 top locked
TP8 "Ø1.5mm,SMD" TP_SMD_Ø1.5mm 65.575,45.625 r0 top locked
TP9 "Ø1.5mm,SMD" TP_SMD_Ø1.5mm 27.597,46.197 r0 top locked
TP10 "Ø0.7mm,SMD" TP_SMD_Ø0.7mm 59.875,38 r0 top locked
TP11 "Ø1.5mm,SMD" TP_SMD_Ø1.5mm 36.49,14.45 r0 top locked
TP12 "Ø1.5mm,SMD" TP_SMD_Ø1.5mm 80.74,24.644 r0 top locked
TP13 "Ø1.5mm,SMD" TP_SMD_Ø1.5mm 24.625,42.539 r0 top locked
TP14 "Ø1.5mm,SMD" TP_SMD_Ø1.5mm 21.625,42.539 r0 top locked
TP15 "Ø1.5mm,SMD" TP_SMD_Ø1.5mm 47.838,38.375 r0 top locked
TP16 "Ø1.5mm,SMD" TP_SMD_Ø1.5mm 53.238,38.375 r0 top locked
TP17 "Ø1.5mm,SMD" TP_SMD_Ø1.5mm 56.225,38.375 r0 top locked
TP18 "Ø0.7mm,SMD" TP_SMD_Ø0.7mm 49.575,51.875 r0 top locked
TP19 "Ø0.7mm,SMD" TP_SMD_Ø0.7mm 80.465,15.419 r0 top locked
TP20 "Ø1.5mm,SMD" TP_SMD_Ø1.5mm 74.625,11.9 r0 top locked
TP21 "Ø0.7mm,SMD" TP_SMD_Ø0.7mm 70.175,47.679 r0 top locked
TP22 "Ø0.7mm,SMD" TP_SMD_Ø0.7mm 74.625,49.25 r0 top locked
TP23 "Ø0.7mm,SMD" TP_SMD_Ø0.7mm 74.625,9.65 r0 top locked
TP24 "Ø0.7mm,SMD" TP_SMD_Ø0.7mm 75.915,17.229 r0 top locked
TP25 "Ø1.5mm,SMD" TP_SMD_Ø1.5mm 12.275,36.55 r0 top locked
TP26 "Ø0.7mm,SMD" TP_SMD_Ø0.7mm 29.375,20.7 r0 top locked
TP27 "Ø1.5mm,SMD" TP_SMD_Ø1.5mm 13.525,34.125 r0 top locked
TP28 "Ø1.5mm,SMD" TP_SMD_Ø1.5mm 50.538,38.375 r0 top locked
TP29 "Ø1.5mm,SMD" TP_SMD_Ø1.5mm 80.74,27.644 r0 top locked
TP30 "Ø0.7mm,SMD" TP_SMD_Ø0.7mm 29.35,21.98 r0 top locked
TP31 "Ø0.7mm,SMD" TP_SMD_Ø0.7mm 29.35,23.25 r0 top locked
TP32 "Ø0.7mm,SMD" TP_SMD_Ø0.7mm 29.35,24.52 r0 top locked
TP33 "Ø0.7mm,SMD" TP_SMD_Ø0.7mm 29.35,25.79 r0 top locked
TP34 "Ø1.5mm,SMD" TP_SMD_Ø1.5mm 12.275,31.75 r0 top locked
TP35 "Ø1.5mm,SMD" TP_SMD_Ø1.5mm 18.71,14.45 r0 top locked
TP36 "Ø1.5mm,SMD" TP_SMD_Ø1.5mm 16.17,14.45 r0 top locked
TP37 "Ø0.7mm,SMD" TP_SMD_Ø0.7mm 35.9,41.65 r90 top
TP38 "Ø0.7mm,SMD" TP_SMD_Ø0.7mm 39.025,39.15 r90 top
TP39 "Ø0.7mm,SMD" TP_SMD_Ø0.7mm 35.695,39.655 r90 top
TP40 "Ø0.7mm,SMD" TP_SMD_Ø0.7mm 29.35,27.06 r90 top
TP41 "Ø0.7mm,SMD" TP_SMD_Ø0.7mm 29.35,28.33 r90 top
U1 "ADA4622" QFN65P400X400X80_HS-17N 64.471,36.181 r0 top locked
U2 "ADA4622" QFN65P400X400X80_HS-17N 74.125,36.181 r270 top locked
U4 "ADP151" SON65P200X60_HS-7N 14.9,47.9 r90 top locked
U5 "ADP5072" BGA20C40P4X5_161X218X56 51.7,47.925 r270 top locked
U6 "ADP7118" SON65P200X60_HS-7N 54.718,41.684 r180 top locked
U7 "24CW160" SOT-23-5 17.725,40.95 r0 top locked
U8 "ADP2504" SON50P300X80-HS-11N 78.89,20.494 r180 top locked
U9 "ADP1708" SON50P300X80_HS-9N 78.89,11.594 r180 top locked
U10 "MCP4451_100k" QFN50P400X400X80_HS-21N 74.125,45.25 r0 top locked
U11 "FXMA108" QFN50P450X250X80_HS-21N 27.575,16.125 r270 top locked
U12 "nRF52840-QIAA" AQFN50P700X700X85_HS-74N 19.14,27 r180 top locked
X1 "32MHz" BT-XTAL_2016 14.879,20.905 r0 top locked

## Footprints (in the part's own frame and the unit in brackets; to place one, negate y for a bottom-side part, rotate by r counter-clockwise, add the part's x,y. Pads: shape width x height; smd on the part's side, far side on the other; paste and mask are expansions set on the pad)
AQFN50P700X700X85_HS-74N [mm] "AQFN, 73-Leads, Body 7.00x7.00mm, Pitch 0.50mm, Thermal Pad 4.95x4.95mm, IPC Medium Density"
  rect 4.85x4.85 smd paste-5 mask+0.05: 74(0,0)
  round 0.275 smd paste+0.012 mask+0.05: A8(-1.25,3.25) A10(-0.75,3.25) A12(-0.25,3.25) A14(0.25,3.25) A16(0.75,3.25) A18(1.25,3.25) A20(1.75,3.25) A22(2.25,3.25) A23(2.75,3.25) AA24(3.25,-2.25) AB2(-2.75,-2.5) AC5(-2,-2.75) AC9(-1,-2.75) AC11(-0.5,-2.75) AC13(0,-2.75) AC15(0.5,-2.75) AC17(1,-2.75) AC19(1.5,-2.75) AC21(2,-2.75) AC24(3.25,-2.75) AD2(-2.75,-3.25) AD4(-2.25,-3.25) AD6(-1.75,-3.25) AD8(-1.25,-3.25) AD10(-0.75,-3.25) AD12(-0.25,-3.25) AD14(0.25,-3.25) AD16(0.75,-3.25) AD18(1.25,-3.25) AD20(1.75,-3.25) AD22(2.25,-3.25) AD23(2.75,-3.25) B1(-3.25,2.75) B3(-2.5,2.75) B5(-2,2.75) B7(-1.5,2.75) B9(-1,2.75) B11(-0.5,2.75) B13(0,2.75) B15(0.5,2.75) B17(1,2.75) B19(1.5,2.75) B24(3.25,2.75) C1(-3.25,2.25) D2(-2.75,2) D23(2.75,2) E24(3.25,1.75) F2(-2.75,1.5) F23(2.75,1.5) G1(-3.25,1.25) H2(-2.75,1) H23(2.75,1) J1(-3.25,0.75) J24(3.25,0.75) K2(-2.75,0.5) L1(-3.25,0.25) L24(3.25,0.25) M2(-2.75,0) N1(-3.25,-0.25) N24(3.25,-0.25) P2(-2.75,-0.5) P23(2.75,-0.5) R1(-3.25,-0.75) R24(3.25,-0.75) T2(-2.75,-1) T23(2.75,-1) U1(-3.25,-1.25) U24(3.25,-1.25) V23(2.75,-1.5) W1(-3.25,-1.75) W24(3.25,-1.75) Y2(-2.75,-2) Y23(2.75,-2)
  rrect15% 0.94x0.94 on Top Paste: ""(-1.71,1.71) ""(-1.71,-0.57) ""(-1.71,0.57) ""(-1.71,-1.71) ""(-0.57,1.71) ""(-0.57,0.57) ""(-0.57,-0.57) ""(-0.57,-1.71) ""(0.57,1.71) ""(0.57,0.57) ""(0.57,-0.57) ""(0.57,-1.71) ""(1.71,1.71) ""(1.71,-0.57) ""(1.71,0.57) ""(1.71,-1.71)
  silkscreen extent -4.57,-3.6 3.6,3.6, body extent -3.5,-3.5 3.5,3.5, height 0.87
BGA6C65P2X3_146X191X22 [mm] "BGA, 6-Leads, Body 1,46x1,91mmx0,22mm, Pitch 0,65mm"
  round 0.3 smd: 1(-0.325,0.65) 2(-0.325,0) 3(-0.325,-0.65) 4(0.325,-0.65) 5(0.325,0) 6(0.325,0.65)
  silkscreen extent -0.87,-1.05 0.83,1.35, body extent -0.73,-0.96 0.73,0.95, height 0.3
BGA20C40P4X5_161X218X56 [mm] "BGA, 20-Leads, Body 1,61x2,18mmx0,56mm, Pitch 0,40mm"
  round 0.21 smd: A1(-0.6,0.8) A2(-0.2,0.8) A3(0.2,0.8) A4(0.6,0.8) B1(-0.6,0.4) B2(-0.2,0.4) B3(0.2,0.4) B4(0.6,0.4) C1(-0.6,0) C2(-0.2,0) C3(0.2,0) C4(0.6,0) D1(-0.6,-0.4) D2(-0.2,-0.4) D3(0.2,-0.4) D4(0.6,-0.4) E1(-0.6,-0.8) E2(-0.2,-0.8) E3(0.2,-0.8) E4(0.6,-0.8)
  silkscreen extent -1.22,-1.2 0.92,1.3, body extent -0.8,-1.09 0.8,1.09, height 0.56
BT-XTAL_2016 [mm] "Crystal 2.0 x 1.6 mm"
  rect 0.95x0.85 smd: 1(-0.725,-0.575) 2(0.725,-0.575) 3(0.725,0.575) 4(-0.725,0.575)
  silkscreen extent -1.08,-0.88 1.08,0.88, body extent -1.05,-0.85 1.05,0.85, height 0.56
CAPC0603X03L_C [mm] "Chip Capacitor, 2-Leads, Body 0.6x0.3mm, IPC High Density"
  rect 0.27x0.3 smd mask+0.05: 1(-0.285,0) 2(0.285,0)
  silkscreen extent -0.49,-0.22 0.49,0.22, body extent -0.3,-0.15 0.31,0.15, height 0.3
CAPC1005X04L [mm] "Chip Capacitor, 2-Leads, Body 1.0x0.5mm, IPC High Density"
  rect 0.6x0.5 smd: 1(-0.5,0) 2(0.5,0)
  silkscreen extent -0.9,-0.35 0.9,0.35, body extent -0.51,-0.25 0.51,0.25, height 0.5
CAPC1005X04L_NC [mm] "Chip Capacitor, 2-Leads, Body 1.0x0.5mm, IPC High Density"
  rect 0.6x0.5 smd: 1(-0.5,0) 2(0.5,0)
  silkscreen extent -0.9,-0.35 0.9,0.35
CAPC1608X06L [mm] "Chip Capacitor, 2-Leads, Body 1.6x0.8mm, IPC High Density"
  rect 0.75x0.8 smd: 1(-0.675,0) 2(0.675,0)
  silkscreen extent -1.17,-0.5 1.17,0.5, body extent -0.8,-0.43 0.8,0.43, height 0.8
DFN65P200X60_HS-6N [mm] "DFN, 6-Leads, Body 2,00x2,00mm, Pitch 0,65mm, IPC Medium Density"
  rect 0.5x0.35 smd: 1(-0.9,0.65) 2(-0.9,0) 3(-0.9,-0.65) 4(0.9,-0.65) 5(0.9,0) 6(0.9,0.65)
  rect 1x0.6 smd: 3(0,-0.525) 6(0,0.525)
  silkscreen extent -1.49,-1.19 1.04,1.24, body extent -1.05,-1.04 1.05,1.04, height 0.61
DFN1006D-2 [mm]
  rect 0.5x0.7 smd: 1(-0.4,0) 2(0.4,0)
  silkscreen extent -0.93,-0.36 -0.93,0.36, body extent -0.53,-0.33 0.52,0.32, height 0.4
ENCLOSURE_PPK2 [mm] "Plastic Enclosure for PPK2"
  body extent -43.05,-27.24 43.05,27.24, height 5.5
Fiducial_Round-Square [mm] "Fiducial Mark"
  rect 1x1 smd paste-10 mask+0.5: 0(0,0)
  Top Layer keep-out lines w0.01: -1,1 -1,-1 1,-1 1,1 -1,1
HDR_2x5-SMD-1.27mm-ANG [mm] "Pin Header Angled, 1.27mm SMD, FTSH-105 series, \"SWD\" version"
  round 1.02 hole 1.02 unplated: 0(-1.905,-4.32) 0(1.905,-4.32)
  rect 0.76x2.03 smd: 1(-2.54,-1.525) 2(-2.54,1.525) 3(-1.27,-1.525) 4(-1.27,1.525) 5(0,-1.525) 6(0,1.525) 7(1.27,-1.525) 8(1.27,1.525) 9(2.54,-1.525) 10(2.54,1.525)
  silkscreen extent -3.17,-5.57 3.17,-3.07, body extent -3.18,-8.63 3.17,2.27, height 3.41
HOLE_PT_3MM [mm] "Regular 4mm plated hole"
  round 5 hole 3 paste+0 mask+0: 1(0,0)
IND_EPL2014 [mm] "IND, 2-Leads, Body 2,00x2,00mm, Pitch 1,35mm, IPC Medium Density"
  rect 0.65x1.85 smd: 1(-0.675,0) 2(0.675,0)
  silkscreen extent -1.28,-1.2 1.28,1.2, body extent -1.1,-1.1 1.1,1.1, height 1.45
INDC1005X04L [mm] "Chip Inductor, 2-Leads, Body 1.0x0.5mm, IPC High Density"
  rect 0.65x0.5 smd: 1(-0.475,0) 2(0.475,0)
  silkscreen extent -0.9,-0.35 0.9,0.35, body extent -0.5,-0.3 0.5,0.3, height 0.5
LIST_ANG_1x4-SMD-2.54MM [mm] "Pin List, 2.54mm, Surface Mount, Angled"
  round 1.78 hole 1.78 unplated: 0(-2.54,-4.496) 0(2.54,-4.496)
  rect 1.27x3.18 smd: 1(-3.81,0) 2(-1.27,0) 3(1.27,0) 4(3.81,0)
  silkscreen extent -5.08,-11.35 5.08,-1.8, body extent -5.1,-11.61 5.06,1.35, height 3.03
LIST_ANG_1x10-SMD-2.54MM [mm] "Pin List, 2.54mm, Surface Mount, Angled"
  round 1.78 hole 1.78 unplated: 0(-10.16,-4.496) 0(10.16,-4.496)
  rect 1.27x3.18 smd: 1(-11.43,0) 2(-8.89,0) 3(-6.35,0) 4(-3.81,0) 5(-1.27,0) 6(1.27,0) 7(3.81,0) 8(6.35,0) 9(8.89,0) 10(11.43,0)
  silkscreen extent -12.7,-11.35 12.7,-1.8, body extent -12.72,-11.61 12.68,1.35, height 3.03
MSL0104 [mm]
  rect 1.06x1.58 smd paste+0: 1(-2.95,0.3) 1(2.95,0.3)
  rect 0.6x2.18 smd paste+0: 2(1.8,0) 3(0.9,0) 4(0,0) 5(-0.9,0) 6(-1.8,0)
  silkscreen extent -3.2,1.3 3.2,1.75, body extent -3.45,-0.4 3.45,1.78, height 2.15
NetTie_200um [mm]
  round 0.2 smd paste-2 mask-2: 1(-0.3,0) 2(0.3,0)
  Top Layer region: -0.3,0.1 -0.3,-0.1 0.3,-0.1 0.3,0.1
QFN50P400X400X80_HS-21N [mm] "QFN, 20-Leads, Body 4.00x4.00mm, Pitch 0.50mm, Thermal Pad 2.70x2.70mm, IPC Medium Density"
  oval 0.8x0.25 smd: 1(-1.95,1) 2(-1.95,0.5) 3(-1.95,0) 4(-1.95,-0.5) 5(-1.95,-1) 11(1.95,-1) 12(1.95,-0.5) 13(1.95,0) 14(1.95,0.5) 15(1.95,1)
  oval 0.25x0.8 smd: 6(-1,-1.95) 7(-0.5,-1.95) 8(0,-1.95) 9(0.5,-1.95) 10(1,-1.95) 16(1,1.95) 17(0.5,1.95) 18(0,1.95) 19(-0.5,1.95) 20(-1,1.95)
  rect 2.7x2.7 smd: 21(0,0)
  silkscreen extent -2.97,-2.2 2.2,2.2, body extent -2.05,-2.05 2.05,2.05, height 0.8
QFN50P450X250X80_HS-21N [mm] "QFN, 20-Leads, Body 4.50x2.50mm, Pitch 0.50mm, Thermal Pad 3.15x1.15mm, IPC Medium Density"
  oval 0.25x0.7 smd: 1(-0.25,2.25) 10(-0.25,-2.25) 11(0.25,-2.25) 20(0.25,2.25)
  oval 0.7x0.25 smd: 2(-1.25,1.75) 3(-1.25,1.25) 4(-1.25,0.75) 5(-1.25,0.25) 6(-1.25,-0.25) 7(-1.25,-0.75) 8(-1.25,-1.25) 9(-1.25,-1.75) 12(1.25,-1.75) 13(1.25,-1.25) 14(1.25,-0.75) 15(1.25,-0.25) 16(1.25,0.25) 17(1.25,0.75) 18(1.25,1.25) 19(1.25,1.75)
  rect 1x2.9 smd: 21(0,0)
  silkscreen extent -1.92,-2.4 1.4,2.93, body extent -1.25,-2.27 1.27,2.25, height 1
QFN65P400X400X80_HS-17N [mm] "QFN, 16-Leads, Body 4,00x4,00mm, Pitch 0,65mm, Thermal Pad 2,35x2,35mm, IPC Medium Density"
  oval 0.95x0.3 smd: 1(-1.875,0.975) 2(-1.875,0.325) 3(-1.875,-0.325) 4(-1.875,-0.975) 9(1.875,-0.975) 10(1.875,-0.325) 11(1.875,0.325) 12(1.875,0.975)
  oval 0.3x0.95 smd: 5(-0.975,-1.875) 6(-0.325,-1.875) 7(0.325,-1.875) 8(0.975,-1.875) 13(0.975,1.875) 14(0.325,1.875) 15(-0.325,1.875) 16(-0.975,1.875)
  rect 2.35x2.35 smd: 17(0,0)
  silkscreen extent -2.97,-2.2 2.2,2.2, body extent -2.07,-2.07 2.07,2.07, height 0.8
RESC0603X03L_C [mm] "Chip Resistor, 2-Leads, Body 0.6x0.3mm, IPC High Density"
  rect 0.27x0.3 smd: 1(-0.285,0) 2(0.285,0)
  silkscreen extent -0.49,-0.22 0.49,0.22, body extent -0.3,-0.15 0.3,0.15, height 0.23
RESC1005X04L [mm] "Chip Resistor, 2-Leads, Body 1.0x0.5mm, IPC High Density"
  rect 0.6x0.55 smd mask+0.05: 1(-0.5,0) 2(0.5,0)
  silkscreen extent -0.87,-0.38 0.88,0.38, body extent -0.5,-0.25 0.5,0.25, height 0.3
RESC2012X11L [mm] "Chip Resistor, 2-Leads, Body 2.0x1.3mm, IPC High Density"
  rect 1.15x1.35 smd: 1(-0.775,0) 2(0.775,0)
  silkscreen extent -1.45,-0.77 1.45,0.77, body extent -1,-0.62 1,0.63, height 0.5
Screw_25x50_pan_tx [mm] "2.5x5.0mm, pan head, t8 screw"
  body extent -2.2,-2.2 2.2,2.2, height 1.9
Solderbridge [mm]
  round 0.2 smd paste-10: 1(-0.312,0) 2(0.312,0)
  Top Layer region: -0.077,-0.432 -0.152,-0.505 -0.271,-0.467 -0.335,-0.424 -0.409,-0.351 -0.462,-0.292 -0.521,-0.193 -0.549,-0.099 -0.544,0.122 -0.518,0.193 -0.434,0.33 -0.351,0.411 -0.259,0.469 -0.157,0.5 -0.107,0.483 -0.077,0.43
  Top Layer region: 0.077,0.432 0.152,0.505 0.271,0.467 0.335,0.424 0.409,0.351 0.462,0.292 0.521,0.193 0.549,0.099 0.544,-0.122 0.518,-0.193 0.434,-0.33 0.351,-0.411 0.259,-0.469 0.157,-0.5 0.107,-0.483 0.077,-0.43
  Top Layer lines w0.152: 0.153,0.431 cw(c0.042,0) 0.25,0.393 cw(c0.042,0) 0.312,0.353 cw(c0.042,0) 0.487,0 cw(c0.042,0) 0.153,-0.431 ; -0.153,0.431 ccw(c-0.042,0) -0.461,0.149 ccw(c-0.042,0) -0.487,0 ccw(c-0.042,0) -0.153,-0.431
SON50P300X80-HS-11N [mm] "SON, 10-Leads, Body 3,00x3,00mm, Pitch 0,50mm, Thermal Pad 2,36x1,49mm, IPC Medium Density"
  rect 0.9x0.25 smd: 1(-1.395,1) 2(-1.395,0.5) 3(-1.395,0) 4(-1.395,-0.5) 5(-1.395,-1) 6(1.395,-1) 7(1.395,-0.5) 8(1.395,0) 9(1.395,0.5) 10(1.395,1)
  rect 1.49x2.36 smd: 11(0,0)
  silkscreen extent -2.1,-1.68 1.67,1.72, body extent -1.57,-1.55 1.57,1.55, height 0.8
SON50P300X80_HS-9N [mm] "SON, 8-Leads, Body 3,00x3,00mm, Pitch 0,50mm, Thermal Pad 1,74x1,45mm, IPC Medium Density"
  oval 0.9x0.25 smd: 1(-1.395,0.75) 2(-1.395,0.25) 3(-1.395,-0.25) 4(-1.395,-0.75) 5(1.395,-0.75) 6(1.395,-0.25) 7(1.395,0.25) 8(1.395,0.75)
  rect 1.45x1.74 smd: 9(0,0)
  silkscreen extent -2.1,-1.67 1.67,1.72, body extent -1.57,-1.55 1.57,1.55, height 0.8
SON65P200X60_HS-7N [mm] "SON, 6-Leads, Body 2,00x2,00mm, Pitch 0,65mm, Thermal Pad 1,60x0,63mm, IPC Medium Density"
  rect 0.655x0.3 smd: 1(-0.978,0.65) 2(-0.978,0) 3(-0.978,-0.65) 4(0.978,-0.65) 5(0.978,0) 6(0.978,0.65)
  rect 0.99x1.6 smd: 7(0,0)
  silkscreen extent -1.47,-1.17 1.05,1.22, body extent -1.07,-1.05 1.07,1.05, height 0.6
SOT190P230X110-4L [mm] "SOT143, 4-Leads, Body 3.0x2.5mm (max), Pitch 1.90mm, IPC High Density"
  rect 0.85x1 smd: 1(-1.025,0.75)
  rect 0.85x0.6 smd: 2(-1.025,-0.95) 3(1.025,-0.95) 4(1.025,0.95)
  silkscreen extent -1.15,-1.5 0.7,1.92, body extent -1.21,-1.46 1.21,1.46, height 1
SOT-23-5 [mm] "SOT-23/SC-74A; 5 Leads; Body 3.1 x 3 mm, inc. leads (LxW max)"
  rect 0.55x1.45 smd: 1(-0.95,-1.075) 2(0,-1.075) 3(0.95,-1.075) 4(0.95,1.075) 5(-0.95,1.075)
  silkscreen extent -1.57,-1.35 1.55,0.9, body extent -1.5,-1.5 1.5,1.5, height 1.3
Switch-Slide-RA-J-Lead-DPDT-8.5x3.5mm [mm] "Slide Switches - DPDT, SMD, ON-ON"
  round 0.9 hole 0.9 unplated mask+0: 0(-3.4,0) 0(3.4,0)
  rect 1x1.6 smd: 1(-2.5,-1.4) 2(0,-1.4) 3(2.5,-1.4) 4(-2.5,1.4) 5(0,1.4) 6(2.5,1.4)
  silkscreen extent -4.5,-3.8 4.5,1.75, body extent -4.25,-3.75 4.25,1.75, height 3.5
TP_SMD_Ø0.7mm [mm]
  round 0.7 smd paste-5: 1(0,0)
  silkscreen extent -0.63,-0.63 0.64,0.63
TP_SMD_Ø1.5mm [mm]
  round 1.5 smd paste-5: 1(0,0)
TY-NR3015 [mm] "Molded Inductor, 2-Leads, Body 3.00x3.00mm, IPC Medium Density"
  rect 0.8x2.7 smd: 1(-1.1,0) 2(1.1,0)
  silkscreen extent -2.05,-1.55 1.55,1.75, body extent -1.5,-1.5 1.5,1.5, height 1.35
UDFN65P200X200X60_HS-6N [mm] "DFN, 6-Leads, Body 2.00x2.00mm, Pitch 0.65mm, IPC Medium Density"
  rect 0.425x0.4 smd mask+0.055: 1(-0.945,-0.65) 2(0.945,-0.65) 3(-0.945,0) 3(-0.945,0.65) 3(0.945,0) 3(0.945,0.65)
  rect 0.8x0.48 smd mask+0.055: 2(0,-0.7)
  rect 1.15x0.95 smd mask+0.055: 3(0,0.325)
  silkscreen extent -1.52,-1.08 1.08,1.08, body extent -1.02,-1.02 1.02,1.02, height 0.8
USB-Micro-B-RA-SMD-PiP [mm] "Micro USB B SMT"
  rect 1.35x0.4 smd mask+0.075: 1(0,1.3) 2(0,0.65) 3(0,0) 4(0,-0.65) 5(0,-1.3)
  oval 1.6x0.9 hole 0.5 slot 1.2 at 0 deg: 6(-2.675,3.3) 6(-2.675,-3.3)
  oval 2x1.5 on Top Paste: 6(-2.675,3.3) 6(-2.675,-3.3)
  rect 1.55x1.9 smd: 6(-2.675,1.2) 6(-2.675,-1.2)
  rect 1.4x1.6 smd: 6(-0.225,3.2) 6(-0.225,-3.2)
  silkscreen extent -4.75,-3.75 0.25,3.75, body extent -5.28,-4.1 0.15,4.1, height 2.72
